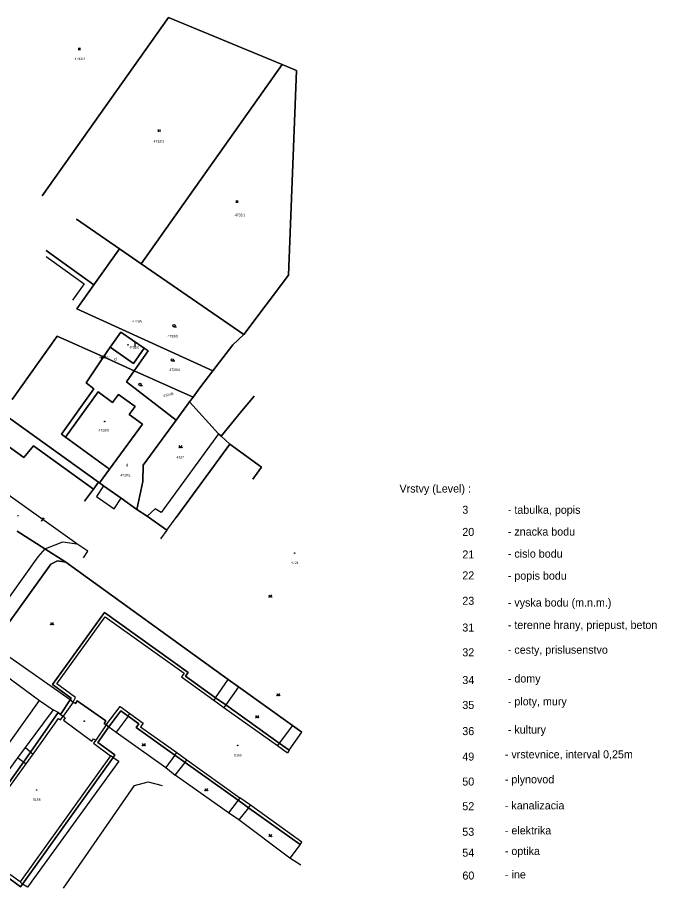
# Model space of a CAD drawing. Extents: x -400488 to -400124, y -1251493 to -1251223.
# Drawn here: x -400248.8 to -400124.3, y -1251402.6 to -1251233 of the extents above; entities that cross this region are included whole.
import ezdxf

# ---------------------------------------------------------------- set-up
doc = ezdxf.new("R2010")
doc.units = 0
doc.layers.add('Level 3', color=7, linetype='Continuous')
doc.layers.add('Level 63', color=7, linetype='Continuous')

msp = doc.modelspace()

# ---------------------------------------------------------------- linework, layer by layer
at = {"layer": 'Level 63'}
for p, q in [((-400219.35, -1251233.04), (-400243.96, -1251267.8)), ((-400243.96, -1251267.8), (-400219.35, -1251233.04)), ((-400197.2, -1251242.23), (-400219.35, -1251233.04)), ((-400219.35, -1251233.04), (-400197.2, -1251242.23)), ((-400236.8, -1251239.4), (-400236.8, -1251238.95)), ((-400236.51, -1251239.4), (-400236.51, -1251238.95)), ((-400197.2, -1251242.23), (-400224.65, -1251281.05)), ((-400224.65, -1251281.05), (-400197.2, -1251242.23)), ((-400194.44, -1251243.37), (-400197.2, -1251242.23)), ((-400197.2, -1251242.23), (-400194.44, -1251243.37)), ((-400195.99, -1251283.23), (-400194.44, -1251243.37)), ((-400194.44, -1251243.37), (-400195.99, -1251283.23)), ((-400221.27, -1251255.34), (-400221.27, -1251254.9)), ((-400220.97, -1251255.34), (-400220.97, -1251254.9)), ((-400206.12, -1251269.16), (-400206.12, -1251268.71)), ((-400205.83, -1251269.16), (-400205.83, -1251268.71)), ((-400237.28, -1251272.34), (-400228.86, -1251278.14)), ((-400228.86, -1251278.14), (-400237.28, -1251272.34)), ((-400243.16, -1251278.43), (-400233.85, -1251285.14)), ((-400233.85, -1251285.14), (-400243.16, -1251278.43)), ((-400228.86, -1251278.14), (-400233.85, -1251285.14)), ((-400233.85, -1251285.14), (-400228.86, -1251278.14)), ((-400228.86, -1251278.14), (-400224.65, -1251281.05)), ((-400224.65, -1251281.05), (-400228.86, -1251278.14)), ((-400243.14, -1251279.62), (-400235.75, -1251284.97)), ((-400243.14, -1251279.62), (-400235.75, -1251284.97)), ((-400224.65, -1251281.05), (-400204.68, -1251294.82)), ((-400204.68, -1251294.82), (-400224.65, -1251281.05)), ((-400204.68, -1251294.82), (-400195.99, -1251283.23)), ((-400195.99, -1251283.23), (-400204.68, -1251294.82)), ((-400235.75, -1251284.97), (-400238.03, -1251288.1)), ((-400235.75, -1251284.97), (-400238.03, -1251288.1)), ((-400233.85, -1251285.14), (-400237.18, -1251289.81)), ((-400237.18, -1251289.81), (-400233.85, -1251285.14)), ((-400237.18, -1251289.81), (-400210.69, -1251301.91)), ((-400210.69, -1251301.91), (-400237.18, -1251289.81)), ((-400218.28, -1251293.3), (-400217.76, -1251293.3)), ((-400247.51, -1251318.79), (-400281.26, -1251294.6)), ((-400281.26, -1251294.6), (-400247.51, -1251318.79)), ((-400240.99, -1251295.17), (-400249.77, -1251307.48)), ((-400249.77, -1251307.48), (-400240.99, -1251295.17)), ((-400240.99, -1251295.17), (-400231.98, -1251299.2)), ((-400231.98, -1251299.2), (-400240.99, -1251295.17)), ((-400230.71, -1251297.31), (-400228.65, -1251294.35)), ((-400228.65, -1251294.35), (-400230.71, -1251297.31)), ((-400228.65, -1251294.35), (-400224.07, -1251297.51)), ((-400224.07, -1251297.51), (-400228.65, -1251294.35)), ((-400206.79, -1251296.84), (-400204.68, -1251294.82)), ((-400204.68, -1251294.82), (-400206.79, -1251296.84)), ((-400225.86, -1251296.23), (-400225.92, -1251296.53)), ((-400225.86, -1251297.13), (-400225.86, -1251296.23)), ((-400225.8, -1251296.53), (-400225.86, -1251296.23)), ((-400210.69, -1251301.91), (-400206.79, -1251296.84)), ((-400206.79, -1251296.84), (-400210.69, -1251301.91)), ((-400231.98, -1251299.2), (-400230.71, -1251297.31)), ((-400230.71, -1251297.31), (-400231.98, -1251299.2)), ((-400230.71, -1251297.31), (-400226.15, -1251300.48)), ((-400226.15, -1251300.48), (-400230.71, -1251297.31)), ((-400226.15, -1251300.48), (-400224.07, -1251297.51)), ((-400224.07, -1251297.51), (-400226.15, -1251300.48)), ((-400223.31, -1251298.01), (-400226, -1251301.88)), ((-400226, -1251301.88), (-400223.31, -1251298.01)), ((-400224.07, -1251297.51), (-400223.31, -1251298.01)), ((-400223.31, -1251298.01), (-400224.07, -1251297.51)), ((-400234.58, -1251303.08), (-400231.98, -1251299.2)), ((-400231.98, -1251299.2), (-400234.58, -1251303.08)), ((-400231.62, -1251299.04), (-400232.45, -1251299.39)), ((-400232.2, -1251299.22), (-400232.45, -1251299.39)), ((-400232.45, -1251299.39), (-400232.15, -1251299.33)), ((-400231.98, -1251299.2), (-400226, -1251301.88)), ((-400226, -1251301.88), (-400231.98, -1251299.2)), ((-400218.62, -1251299.98), (-400218.1, -1251299.98)), ((-400226, -1251301.88), (-400227.5, -1251304.03)), ((-400227.5, -1251304.03), (-400226, -1251301.88)), ((-400214.54, -1251307), (-400226, -1251301.88)), ((-400226, -1251301.88), (-400214.54, -1251307)), ((-400213.22, -1251305.2), (-400210.69, -1251301.91)), ((-400210.69, -1251301.91), (-400213.22, -1251305.2)), ((-400235.36, -1251304.24), (-400234.58, -1251303.08)), ((-400234.58, -1251303.08), (-400235.36, -1251304.24)), ((-400240.15, -1251314.24), (-400233.87, -1251305.41)), ((-400233.87, -1251305.41), (-400240.15, -1251314.24)), ((-400233.87, -1251305.41), (-400235.36, -1251304.24)), ((-400235.36, -1251304.24), (-400233.87, -1251305.41)), ((-400227.5, -1251304.03), (-400217.84, -1251311.51)), ((-400217.84, -1251311.51), (-400227.5, -1251304.03)), ((-400224.9, -1251304.73), (-400224.38, -1251304.73)), ((-400214.54, -1251307), (-400213.22, -1251305.2)), ((-400213.22, -1251305.2), (-400214.54, -1251307)), ((-400239.42, -1251314.82), (-400233.05, -1251306)), ((-400233.05, -1251306), (-400239.42, -1251314.82)), ((-400233.05, -1251306), (-400230.24, -1251308.05)), ((-400230.24, -1251308.05), (-400233.05, -1251306)), ((-400230.24, -1251308.05), (-400229.1, -1251306.49)), ((-400229.1, -1251306.49), (-400230.24, -1251308.05)), ((-400229.1, -1251306.49), (-400225.81, -1251308.85)), ((-400225.81, -1251308.85), (-400229.1, -1251306.49)), ((-400215.23, -1251307.95), (-400214.54, -1251307)), ((-400214.54, -1251307), (-400215.23, -1251307.95)), ((-400205.03, -1251309.67), (-400202.69, -1251306.8)), ((-400202.69, -1251306.8), (-400205.03, -1251309.67)), ((-400225.81, -1251308.85), (-400226.99, -1251310.42)), ((-400226.99, -1251310.42), (-400225.81, -1251308.85)), ((-400217.84, -1251311.51), (-400215.23, -1251307.95)), ((-400215.23, -1251307.95), (-400217.84, -1251311.51)), ((-400215.23, -1251307.95), (-400209.59, -1251314.18)), ((-400209.59, -1251314.18), (-400215.23, -1251307.95)), ((-400251.66, -1251310.14), (-400232.95, -1251323.57)), ((-400232.95, -1251323.57), (-400251.66, -1251310.14)), ((-400226.99, -1251310.42), (-400224.42, -1251312.29)), ((-400224.42, -1251312.29), (-400226.99, -1251310.42)), ((-400209.09, -1251314.65), (-400205.03, -1251309.67)), ((-400205.03, -1251309.67), (-400209.09, -1251314.65)), ((-400224.42, -1251312.29), (-400230.8, -1251321.04)), ((-400230.8, -1251321.04), (-400224.42, -1251312.29)), ((-400224.3, -1251320.29), (-400217.84, -1251311.51)), ((-400217.84, -1251311.51), (-400224.3, -1251320.29)), ((-400239.42, -1251314.82), (-400240.15, -1251314.24)), ((-400240.15, -1251314.24), (-400239.42, -1251314.82)), ((-400230.8, -1251321.04), (-400239.42, -1251314.82)), ((-400239.42, -1251314.82), (-400230.8, -1251321.04)), ((-400209.59, -1251314.18), (-400220.79, -1251329.52)), ((-400209.59, -1251314.18), (-400220.79, -1251329.52)), ((-400209.59, -1251314.18), (-400209.09, -1251314.65)), ((-400209.09, -1251314.65), (-400209.59, -1251314.18)), ((-400207.4, -1251316.19), (-400209.09, -1251314.65)), ((-400209.09, -1251314.65), (-400207.4, -1251316.19)), ((-400245.64, -1251316.5), (-400247.51, -1251318.79)), ((-400247.51, -1251318.79), (-400245.64, -1251316.5)), ((-400233.96, -1251324.94), (-400245.64, -1251316.5)), ((-400245.64, -1251316.5), (-400233.96, -1251324.94)), ((-400217.83, -1251330.45), (-400207.4, -1251316.19)), ((-400207.4, -1251316.19), (-400217.83, -1251330.45)), ((-400217.3, -1251316.46), (-400217, -1251316.91)), ((-400217, -1251316.91), (-400216.7, -1251316.46)), ((-400201.25, -1251320.69), (-400207.4, -1251316.19)), ((-400207.4, -1251316.19), (-400201.25, -1251320.69)), ((-400224.35, -1251323.47), (-400224.3, -1251320.29)), ((-400224.3, -1251320.29), (-400224.35, -1251323.47)), ((-400202.94, -1251323), (-400201.25, -1251320.69)), ((-400201.25, -1251320.69), (-400202.94, -1251323)), ((-400232.75, -1251323.71), (-400230.8, -1251321.04)), ((-400230.8, -1251321.04), (-400232.75, -1251323.71)), ((-400232.95, -1251323.57), (-400233.96, -1251324.94)), ((-400233.96, -1251324.94), (-400232.95, -1251323.57)), ((-400231.97, -1251324.27), (-400233.37, -1251326.35)), ((-400232.95, -1251323.57), (-400232.75, -1251323.71)), ((-400232.75, -1251323.71), (-400232.95, -1251323.57)), ((-400232.75, -1251323.71), (-400231.97, -1251324.27)), ((-400231.97, -1251324.27), (-400232.75, -1251323.71)), ((-400231.97, -1251324.27), (-400228.57, -1251326.71)), ((-400228.57, -1251326.71), (-400231.97, -1251324.27)), ((-400225.49, -1251328.92), (-400224.35, -1251323.47)), ((-400224.35, -1251323.47), (-400225.49, -1251328.92)), ((-400235.69, -1251327.29), (-400233.96, -1251324.94)), ((-400233.96, -1251324.94), (-400235.69, -1251327.29)), ((-400237.21, -1251335.61), (-400250.54, -1251326.08)), ((-400233.37, -1251326.35), (-400229.93, -1251328.78)), ((-400229.93, -1251328.78), (-400228.57, -1251326.71)), ((-400228.57, -1251326.71), (-400225.49, -1251328.92)), ((-400225.49, -1251328.92), (-400228.57, -1251326.71)), ((-400223.52, -1251330.23), (-400225.49, -1251328.92)), ((-400225.49, -1251328.92), (-400223.52, -1251330.23)), ((-400221.92, -1251328.76), (-400223.52, -1251330.23)), ((-400221.92, -1251328.76), (-400223.52, -1251330.23)), ((-400220.79, -1251329.52), (-400221.92, -1251328.76)), ((-400220.79, -1251329.52), (-400221.92, -1251328.76)), ((-400248.76, -1251330.05), (-400248.54, -1251330.1)), ((-400244.22, -1251331.04), (-400244, -1251331.09)), ((-400243.88, -1251330.99), (-400243.87, -1251330.7)), ((-400243.75, -1251330.6), (-400243.53, -1251330.65)), ((-400219.67, -1251332.97), (-400223.52, -1251330.23)), ((-400223.52, -1251330.23), (-400219.67, -1251332.97)), ((-400219.67, -1251332.97), (-400217.83, -1251330.45)), ((-400219.67, -1251332.97), (-400217.83, -1251330.45)), ((-400248.79, -1251333.14), (-400243.42, -1251336.59)), ((-400243.42, -1251336.59), (-400248.79, -1251333.14)), ((-400219.67, -1251332.97), (-400220.87, -1251334.6)), ((-400242.91, -1251336.39), (-400239.93, -1251335.23)), ((-400239.93, -1251335.23), (-400237.21, -1251335.61)), ((-400235.05, -1251337.05), (-400237.21, -1251335.61)), ((-400243.42, -1251336.59), (-400244.75, -1251338.16)), ((-400243.42, -1251336.59), (-400242.91, -1251336.39)), ((-400243.42, -1251336.59), (-400239.33, -1251339.2)), ((-400239.33, -1251339.2), (-400243.42, -1251336.59)), ((-400235.89, -1251338.3), (-400235.05, -1251337.05)), ((-400244.75, -1251338.16), (-400287.97, -1251398.37)), ((-400242.23, -1251339.57), (-400240.93, -1251338.93)), ((-400240.93, -1251338.93), (-400242.23, -1251339.57)), ((-400240.93, -1251338.93), (-400239.33, -1251339.2)), ((-400239.33, -1251339.2), (-400240.93, -1251338.93)), ((-400239.33, -1251339.2), (-400207.73, -1251362.06)), ((-400207.73, -1251362.06), (-400239.33, -1251339.2)), ((-400253.66, -1251355.39), (-400242.23, -1251339.57)), ((-400242.23, -1251339.57), (-400253.66, -1251355.39)), ((-400199.82, -1251345.55), (-400199.52, -1251346)), ((-400199.52, -1251346), (-400199.22, -1251345.55)), ((-400231.8, -1251348.97), (-400241.95, -1251363.02)), ((-400241.95, -1251363.02), (-400231.8, -1251348.97)), ((-400215.48, -1251360.67), (-400231.8, -1251348.97)), ((-400231.8, -1251348.97), (-400215.48, -1251360.67)), ((-400242.34, -1251350.94), (-400242.04, -1251351.39)), ((-400242.04, -1251351.39), (-400241.74, -1251350.94)), ((-400241.11, -1251362.89), (-400231.66, -1251349.81)), ((-400231.66, -1251349.81), (-400216.32, -1251360.81)), ((-400238.5, -1251366.01), (-400253.66, -1251355.39)), ((-400255.52, -1251358), (-400244.43, -1251366.11)), ((-400216.32, -1251360.81), (-400216.84, -1251361.54)), ((-400216.84, -1251361.54), (-400210.5, -1251366.07)), ((-400216.01, -1251361.4), (-400215.48, -1251360.67)), ((-400215.48, -1251360.67), (-400216.01, -1251361.4)), ((-400210.16, -1251365.58), (-400216.01, -1251361.4)), ((-400216.01, -1251361.4), (-400210.16, -1251365.58)), ((-400241.95, -1251363.02), (-400238.27, -1251365.68)), ((-400238.27, -1251365.68), (-400241.95, -1251363.02)), ((-400237.43, -1251365.55), (-400241.11, -1251362.89)), ((-400210.16, -1251365.58), (-400207.73, -1251362.06)), ((-400207.73, -1251362.06), (-400205.74, -1251363.43)), ((-400205.74, -1251363.43), (-400207.73, -1251362.06)), ((-400205.74, -1251363.43), (-400208.2, -1251366.98)), ((-400205.74, -1251363.43), (-400195.18, -1251370.99)), ((-400195.18, -1251370.99), (-400205.74, -1251363.43)), ((-400198.27, -1251364.75), (-400197.97, -1251365.2)), ((-400197.97, -1251365.2), (-400197.67, -1251364.75)), ((-400263.14, -1251392.28), (-400244.43, -1251366.11)), ((-400244.43, -1251366.11), (-400241.8, -1251367.95)), ((-400238.5, -1251366.01), (-400240.35, -1251368.84)), ((-400240.35, -1251368.84), (-400238.5, -1251366.01)), ((-400237.89, -1251366.42), (-400239.86, -1251369.19)), ((-400238.27, -1251365.68), (-400238.5, -1251366.01)), ((-400238.5, -1251366.01), (-400238.27, -1251365.68)), ((-400237.89, -1251366.42), (-400238.5, -1251366.01)), ((-400238.5, -1251366.01), (-400237.89, -1251366.42)), ((-400237.89, -1251366.42), (-400237.43, -1251365.55)), ((-400237.48, -1251366.7), (-400237.89, -1251366.42)), ((-400237.89, -1251366.42), (-400237.48, -1251366.7)), ((-400237.14, -1251366.21), (-400237.48, -1251366.7)), ((-400237.48, -1251366.7), (-400237.14, -1251366.21)), ((-400231.52, -1251370.11), (-400237.14, -1251366.21)), ((-400237.14, -1251366.21), (-400231.52, -1251370.11)), ((-400210.16, -1251365.58), (-400210.5, -1251366.07)), ((-400210.5, -1251366.07), (-400208.54, -1251367.47)), ((-400208.2, -1251366.98), (-400210.16, -1251365.58)), ((-400210.16, -1251365.58), (-400208.2, -1251366.98)), ((-400241.8, -1251367.95), (-400247.27, -1251375.28)), ((-400240.84, -1251368.49), (-400241.8, -1251367.95)), ((-400231.45, -1251370.88), (-400228.77, -1251367.32)), ((-400228.63, -1251368.16), (-400230.97, -1251371.24)), ((-400230.97, -1251371.24), (-400228.63, -1251368.16)), ((-400228.77, -1251367.32), (-400226.85, -1251368.68)), ((-400227.2, -1251369.17), (-400228.63, -1251368.16)), ((-400228.63, -1251368.16), (-400227.2, -1251369.17)), ((-400208.2, -1251366.98), (-400208.54, -1251367.47)), ((-400208.54, -1251367.47), (-400198.14, -1251374.9)), ((-400197.79, -1251374.41), (-400208.2, -1251366.98)), ((-400208.2, -1251366.98), (-400197.79, -1251374.41)), ((-400240.84, -1251368.49), (-400246.19, -1251376.2)), ((-400246.19, -1251376.2), (-400240.84, -1251368.49)), ((-400245.7, -1251376.55), (-400240.75, -1251369.65)), ((-400240.35, -1251368.84), (-400240.84, -1251368.49)), ((-400240.84, -1251368.49), (-400240.35, -1251368.84)), ((-400240.75, -1251369.65), (-400240.39, -1251369.91)), ((-400240.39, -1251369.91), (-400239.86, -1251369.19)), ((-400240.35, -1251368.84), (-400239.86, -1251369.19)), ((-400239.86, -1251369.19), (-400239.46, -1251369.49)), ((-400239.46, -1251369.49), (-400239.81, -1251369.97)), ((-400239.81, -1251369.97), (-400234.28, -1251374.04)), ((-400227.2, -1251369.17), (-400229.56, -1251372.3)), ((-400227.2, -1251369.17), (-400226.85, -1251368.68)), ((-400225.11, -1251370.65), (-400227.2, -1251369.17)), ((-400227.2, -1251369.17), (-400225.11, -1251370.65)), ((-400226.85, -1251368.68), (-400224.27, -1251370.51)), ((-400202.38, -1251369.02), (-400202.08, -1251369.47)), ((-400202.08, -1251369.47), (-400201.78, -1251369.02)), ((-400231.45, -1251370.88), (-400233.52, -1251373.85)), ((-400230.97, -1251371.24), (-400233.09, -1251374.29)), ((-400233.09, -1251374.29), (-400230.97, -1251371.24)), ((-400231.85, -1251370.6), (-400231.52, -1251370.11)), ((-400231.52, -1251370.11), (-400231.85, -1251370.6)), ((-400231.45, -1251370.88), (-400231.85, -1251370.6)), ((-400231.85, -1251370.6), (-400231.45, -1251370.88)), ((-400230.97, -1251371.24), (-400231.45, -1251370.88)), ((-400231.45, -1251370.88), (-400230.97, -1251371.24)), ((-400230.97, -1251371.24), (-400229.56, -1251372.3)), ((-400225.62, -1251371.37), (-400225.11, -1251370.65)), ((-400225.11, -1251370.65), (-400225.62, -1251371.37)), ((-400218.08, -1251376.76), (-400225.62, -1251371.37)), ((-400225.62, -1251371.37), (-400218.08, -1251376.76)), ((-400224.27, -1251370.51), (-400224.78, -1251371.23)), ((-400224.78, -1251371.23), (-400217.73, -1251376.27)), ((-400195.18, -1251370.99), (-400197.79, -1251374.41)), ((-400195.18, -1251370.99), (-400193.37, -1251372.32)), ((-400193.37, -1251372.32), (-400195.18, -1251370.99)), ((-400229.56, -1251372.3), (-400219.89, -1251379.17)), ((-400195.84, -1251375.81), (-400193.37, -1251372.32)), ((-400234.28, -1251374.04), (-400233.92, -1251373.56)), ((-400233.52, -1251373.85), (-400233.93, -1251374.41)), ((-400233.93, -1251374.41), (-400230.63, -1251376.89)), ((-400233.92, -1251373.56), (-400233.52, -1251373.85)), ((-400233.09, -1251374.29), (-400229.8, -1251376.71)), ((-400229.8, -1251376.71), (-400233.09, -1251374.29)), ((-400224.45, -1251374.5), (-400224.15, -1251374.95)), ((-400224.15, -1251374.95), (-400223.85, -1251374.5)), ((-400197.79, -1251374.41), (-400198.14, -1251374.9)), ((-400198.14, -1251374.9), (-400196.19, -1251376.3)), ((-400195.84, -1251375.81), (-400197.79, -1251374.41)), ((-400197.79, -1251374.41), (-400195.84, -1251375.81)), ((-400247.27, -1251375.28), (-400248.75, -1251377.31)), ((-400246.19, -1251376.2), (-400247.56, -1251378.11)), ((-400247.56, -1251378.11), (-400246.19, -1251376.2)), ((-400246.19, -1251376.2), (-400247.27, -1251375.28)), ((-400247.07, -1251378.46), (-400245.7, -1251376.55)), ((-400246.19, -1251376.2), (-400245.7, -1251376.55)), ((-400229.8, -1251376.71), (-400230.13, -1251377.22)), ((-400230.13, -1251377.22), (-400229.8, -1251376.71)), ((-400218.08, -1251376.76), (-400219.89, -1251379.17)), ((-400218.08, -1251376.76), (-400217.73, -1251376.27)), ((-400216.09, -1251378.19), (-400218.08, -1251376.76)), ((-400218.08, -1251376.76), (-400216.09, -1251378.19)), ((-400217.73, -1251376.27), (-400215.74, -1251377.7)), ((-400195.84, -1251375.81), (-400196.19, -1251376.3)), ((-400248.75, -1251377.31), (-400253.7, -1251384.13)), ((-400247.56, -1251378.11), (-400252.58, -1251385.1)), ((-400252.58, -1251385.1), (-400247.56, -1251378.11)), ((-400252.09, -1251385.45), (-400247.07, -1251378.46)), ((-400247.56, -1251378.11), (-400248.75, -1251377.31)), ((-400230.63, -1251376.89), (-400248.24, -1251401.44)), ((-400230.13, -1251377.22), (-400247.77, -1251401.93)), ((-400247.77, -1251401.93), (-400230.13, -1251377.22)), ((-400247.56, -1251378.11), (-400247.07, -1251378.46)), ((-400229.03, -1251377.93), (-400246.82, -1251402.49)), ((-400230.13, -1251377.22), (-400230.63, -1251376.89)), ((-400230.13, -1251377.22), (-400229.03, -1251377.93)), ((-400218.02, -1251380.69), (-400216.09, -1251378.19)), ((-400216.09, -1251378.19), (-400215.74, -1251377.7)), ((-400205.78, -1251385.57), (-400216.09, -1251378.19)), ((-400216.09, -1251378.19), (-400205.78, -1251385.57)), ((-400215.74, -1251377.7), (-400205.43, -1251385.08)), ((-400219.89, -1251379.17), (-400218.02, -1251380.69)), ((-400207.64, -1251387.99), (-400218.02, -1251380.69)), ((-400239.81, -1251402.68), (-400225.97, -1251382.68)), ((-400225.97, -1251382.68), (-400223.32, -1251381.99)), ((-400223.32, -1251381.99), (-400220.58, -1251382.7)), ((-400212.28, -1251383.3), (-400211.98, -1251383.75)), ((-400211.98, -1251383.75), (-400211.68, -1251383.3)), ((-400205.43, -1251385.08), (-400205.78, -1251385.57)), ((-400203.39, -1251386.54), (-400205.43, -1251385.08)), ((-400205.78, -1251385.57), (-400207.64, -1251387.99)), ((-400203.74, -1251387.03), (-400205.78, -1251385.57)), ((-400205.78, -1251385.57), (-400203.74, -1251387.03)), ((-400203.74, -1251387.03), (-400203.39, -1251386.54)), ((-400193.36, -1251393.73), (-400203.39, -1251386.54)), ((-400205.64, -1251389.38), (-400207.64, -1251387.99)), ((-400203.74, -1251387.03), (-400205.64, -1251389.38)), ((-400193.71, -1251394.21), (-400203.74, -1251387.03)), ((-400203.74, -1251387.03), (-400193.71, -1251394.21)), ((-400195.69, -1251396.83), (-400205.64, -1251389.38)), ((-400199.8, -1251392.19), (-400199.5, -1251392.64)), ((-400199.5, -1251392.64), (-400199.2, -1251392.19)), ((-400193.71, -1251394.21), (-400193.36, -1251393.73)), ((-400193.71, -1251394.21), (-400195.69, -1251396.83)), ((-400193.58, -1251398.19), (-400195.69, -1251396.83)), ((-400248.24, -1251401.44), (-400251.61, -1251399.02)), ((-400248.13, -1251402.41), (-400251.46, -1251399.94)), ((-400251.46, -1251399.94), (-400248.13, -1251402.41)), ((-400247.77, -1251401.93), (-400248.24, -1251401.44)), ((-400247.77, -1251401.93), (-400248.13, -1251402.41)), ((-400248.13, -1251402.41), (-400247.77, -1251401.93)), ((-400246.82, -1251402.49), (-400247.77, -1251401.93))]:
    msp.add_line(p, q, dxfattribs=at)
for centre, radius in [((-400218.28, -1251293.07), 0.225), ((-400227.22, -1251296.84), 0.054), ((-400218.62, -1251299.76), 0.225), ((-400224.9, -1251304.51), 0.225), ((-400231.75, -1251311.77), 0.054), ((-400217.27, -1251316.88), 0.03), ((-400216.73, -1251316.88), 0.03), ((-400194.78, -1251337.4), 0.054), ((-400199.79, -1251345.97), 0.03), ((-400199.25, -1251345.97), 0.03), ((-400242.31, -1251351.36), 0.03), ((-400241.77, -1251351.36), 0.03), ((-400198.24, -1251365.17), 0.03), ((-400197.7, -1251365.17), 0.03), ((-400202.35, -1251369.44), 0.03), ((-400201.81, -1251369.44), 0.03), ((-400235.74, -1251370.15), 0.054), ((-400224.42, -1251374.92), 0.03), ((-400223.88, -1251374.92), 0.03), ((-400205.86, -1251374.88), 0.054), ((-400245.01, -1251383.55), 0.054), ((-400212.25, -1251383.72), 0.03), ((-400211.71, -1251383.72), 0.03), ((-400199.77, -1251392.61), 0.03), ((-400199.23, -1251392.61), 0.03)]:
    msp.add_circle(centre, radius, dxfattribs=at)
for centre, start, end in [((-400243.98, -1251330.99), 257.753, 357.7631), ((-400243.77, -1251330.7), 77.7527, 177.7631)]:
    msp.add_arc(centre, 0.1, start, end, dxfattribs=at)

# ---------------------------------------------------------------- texts
at = {"layer": 'Level 3'}
for s, p in [('Vrstvy (Level) :', (-400174.36, -1251325.61)), ('3', (-400162.13, -1251329.74)), (' - tabulka, popis', (-400153.85, -1251329.75)), ('20', (-400162.13, -1251334.06)), (' - znacka bodu', (-400153.85, -1251334)), ('21', (-400162.13, -1251338.45)), (' - cislo bodu', (-400153.85, -1251338.29)), ('22', (-400162.13, -1251342.53)), (' - popis bodu', (-400153.85, -1251342.59)), ('23', (-400162.13, -1251347.48)), (' - vyska bodu (m.n.m.)', (-400153.85, -1251347.82)), ('31', (-400162.13, -1251352.69)), (' - terenne hrany, priepust, beton', (-400153.85, -1251352.18)), ('32', (-400162.13, -1251357.52)), (' - cesty, prislusenstvo', (-400153.85, -1251357.01)), ('34', (-400162.13, -1251362.92)), (' - domy', (-400153.85, -1251362.62)), ('35', (-400162.13, -1251367.77)), (' - ploty, mury', (-400153.85, -1251367.08)), ('36', (-400162.13, -1251372.87)), (' - kultury', (-400153.85, -1251372.57)), ('49', (-400162.13, -1251377.83)), ('- vrstevnice, interval 0,25m', (-400153.85, -1251377.39)), ('50', (-400162.13, -1251382.7)), ('- plynovod', (-400153.85, -1251382.26)), ('52', (-400162.13, -1251387.5)), ('- kanalizacia', (-400153.85, -1251387.34)), ('53', (-400162.13, -1251392.48)), ('- elektrika', (-400153.85, -1251392.21)), ('54', (-400162.13, -1251396.55)), ('- optika', (-400153.85, -1251396.23)), ('60', (-400162.11, -1251401.01)), (' - ine', (-400154.4, -1251400.79))]:
    msp.add_text(s, height=1.56, dxfattribs=at).set_placement(p)
at = {"layer": 'Level 63'}
for s, height, p in [('4732/4', 0.48, (-400237.62, -1251241.34)), ('4732/3', 0.48, (-400222.24, -1251257.43)), ('4732/1', 0.48, (-400206.44, -1251271.77)), ('4728/6', 0.45, (-400226.37, -1251292.48)), ('4729/5', 0.48, (-400219.5, -1251295.38)), ('4728/6', 0.45, (-400227, -1251297.58)), ('4728/7', 0.48, (-400232.82, -1251299.52)), ('d', 0.6, (-400229.9, -1251299.92)), ('4729/4', 0.48, (-400219.17, -1251301.92)), ('4728/5', 0.48, (-400232.98, -1251313.69)), ('4727', 0.48, (-400217.78, -1251318.99)), ('d', 0.6, (-400227.64, -1251320.52)), ('4728/1', 0.48, (-400228.71, -1251322.47)), ('4721', 0.48, (-400195.47, -1251339.53)), ('5160', 0.48, (-400206.56, -1251377.01)), ('5158', 0.48, (-400245.72, -1251385.68))]:
    msp.add_text(s, height=height, dxfattribs=at).set_placement(p)
msp.add_text('4729/3', height=0.48, rotation=13.31, dxfattribs=at).set_placement((-400220.3, -1251307.02))

doc.saveas('drawing.dxf')
